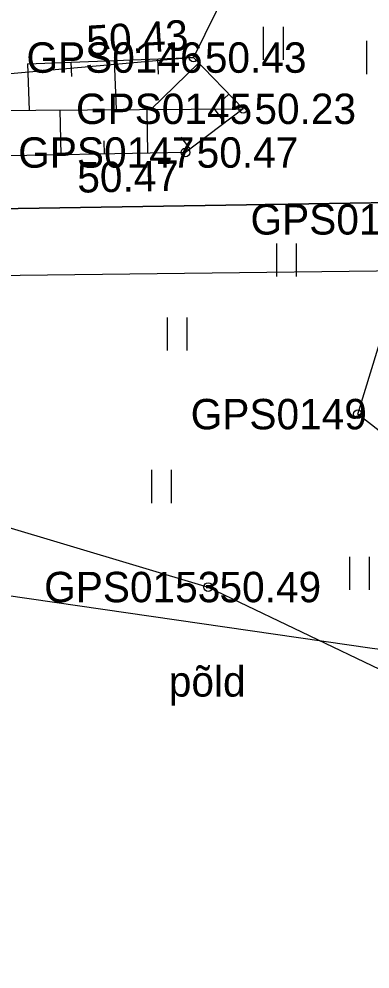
# Model space of a CAD drawing. Extents: x 551623 to 559850, y 6561220 to 6567135.
# Drawn here: x 555977.24 to 555985.32, y 6565343.22 to 6565365.09 of the extents above; entities that cross this region are included whole.
import ezdxf

# ---------------------------------------------------------------- set-up
doc = ezdxf.new("R2010")
doc.units = 0
for name, color, linetype in [('HALJASTUS', 7, 'Continuous'), ('KORGUS-EH2000', 7, 'Continuous'), ('KPOHULIIN', 7, 'Continuous'), ('MOOTKORG-EH2000', 7, 'Continuous'), ('MOOTMPUNKT', 7, 'Continuous'), ('MOOTNR', 7, 'Continuous'), ('MOOTPIIR', 7, 'Continuous'), ('PIIR', 7, 'Continuous'), ('RELJEEF', 7, 'Continuous')]:
    doc.layers.add(name, color=color, linetype=linetype)

msp = doc.modelspace()

# ---------------------------------------------------------------- linework, layer by layer
at = {"layer": 'HALJASTUS'}
for p, q in [((555982.865, 6565364.914), (555982.865, 6565364.153)), ((555983.32, 6565364.914), (555983.32, 6565364.153)), ((555985.243, 6565364.585), (555985.243, 6565363.823)), ((555983.168, 6565359.924), (555983.168, 6565359.162)), ((555983.623, 6565359.924), (555983.623, 6565359.162)), ((555980.649, 6565358.222), (555980.649, 6565357.461)), ((555981.104, 6565358.222), (555981.104, 6565357.461)), ((555980.288, 6565354.709), (555980.288, 6565353.947)), ((555980.743, 6565354.709), (555980.743, 6565353.947)), ((555984.853, 6565352.708), (555984.853, 6565351.947)), ((555985.308, 6565352.708), (555985.308, 6565351.947))]:
    msp.add_line(p, q, dxfattribs=at)
msp.add_lwpolyline([(555785.422, 6565354.502), (555797.657, 6565356.597), (555822.006, 6565356.167), (555839.027, 6565357.099), (555858.223, 6565356.795), (555871.496, 6565354.829), (555880.675, 6565355.554), (555884.247, 6565356.161), (555900.004, 6565357.858), (555919.022, 6565357.654), (555943.248, 6565358.425), (555955.251, 6565358.554), (555967.126, 6565356.336), (555981.596, 6565352.013), (555991.477, 6565347.286)], dxfattribs=at)
at = {"layer": 'KORGUS-EH2000'}
for centre in [(555981.259, 6565364.203), (555981.07, 6565362.017), (555985.042, 6565355.994), (555981.596, 6565352.013)]:
    msp.add_circle(centre, 0.1, dxfattribs=at)
at = {"layer": 'KPOHULIIN'}
msp.add_lwpolyline([(555766.29, 6565358.132), (555774.476, 6565357.809), (555774.476, 6565357.809), (555822.758, 6565358.143), (555870.36, 6565358.416), (555918.911, 6565358.624), (555918.911, 6565358.624), (555966.511, 6565359.063), (556012.012, 6565359.614), (556063.102, 6565345.172), (556063.102, 6565345.172), (556112.628, 6565331.115), (556160.567, 6565309.951), (556211.02, 6565287.529)], dxfattribs=at)
at = {"layer": 'MOOTMPUNKT'}
for centre in [(555981.259, 6565364.203), (555982.4, 6565363.023), (555981.07, 6565362.017), (555985.042, 6565355.994), (555981.596, 6565352.013)]:
    msp.add_circle(centre, 0.1, dxfattribs=at)
at = {"layer": 'MOOTPIIR'}
for points in [[(556057.929, 6565353.821), (556039.198, 6565356.19), (556028.747, 6565357.937), (556026.171, 6565358.357), (556019.769, 6565359.212), (556019.902, 6565364.745), (556021.558, 6565374.265), (556015.152, 6565374.331), (556012.73, 6565375.394), (555993.907, 6565375.821), (555986.511, 6565374.867), (555981.259, 6565364.203), (555966.865, 6565362.926), (555942.733, 6565362.646), (555918.997, 6565362.459), (555899.983, 6565361.794), (555880.558, 6565361.528), (555870.644, 6565361.764), (555852.219, 6565361.421)], [(555839.435, 6565355.215), (555871.496, 6565354.829), (555900.084, 6565356.085), (555918.855, 6565355.549), (555942.97, 6565356.268), (555966.756, 6565353.298), (555985.371, 6565350.605), (555996.731, 6565349.216), (556009.016, 6565348.025), (556019.674, 6565346.939), (556026.62, 6565346.439), (556031.505, 6565345.235), (556038.736, 6565344.782), (556063.163, 6565343.594)]]:
    msp.add_lwpolyline(points, dxfattribs=at)
at = {"layer": 'PIIR'}
for points in [[(555860.69, 6565787.05), (556134.83, 6565867.67), (556136.76, 6565868.24), (556138.68, 6565868.81), (556304.72, 6565917.64), (556407.28, 6565947.65), (556409.2, 6565948.21), (556411.12, 6565948.77), (556555.39, 6565990.98), (556602.55, 6565855.41), (556340.11, 6565662.55), (556145.23, 6565518.55), (556122.95, 6565328.71), (556065.95, 6565349.3), (555986.85, 6565360.88), (555889.86, 6565359.34), (555877.35, 6565546.73)], [(555766.77, 6565362.31), (555785.15, 6565359.9), (555792.17, 6565359.86), (555889.86, 6565359.34), (555986.85, 6565360.88), (556065.95, 6565349.3), (556122.95, 6565328.71), (556199.38, 6565295.85), (556198.85, 6565282.81), (556195.83, 6565275.41), (556189.32, 6565262.35), (556176.88, 6565235.57), (556133.25, 6565139.15), (556097.67, 6565060.64), (555982.17, 6564796.57), (555965.54, 6564731.83), (555935.2, 6564801.96), (555871.92, 6565015.39), (555870.22, 6565021.13), (555867.36, 6565030.76)]]:
    msp.add_lwpolyline(points, close=True, dxfattribs=at)
at = {"layer": 'RELJEEF'}
for p, q in [((555977.434, 6565364.06), (555977.474, 6565362.992)), ((555978.433, 6565364.098), (555978.446, 6565363.768)), ((555979.433, 6565364.135), (555979.475, 6565363.005)), ((555981.379, 6565364.079), (555980.273, 6565363.01)), ((555980.432, 6565364.172), (555980.445, 6565363.824)), ((555982.074, 6565363.361), (555981.968, 6565363.258)), ((555978.208, 6565361.963), (555978.189, 6565362.997)), ((555980.207, 6565362.001), (555980.189, 6565363.009)), ((555981.977, 6565362.703), (555981.738, 6565363.019)), ((555979.208, 6565361.982), (555979.202, 6565362.288)), ((555981.179, 6565362.1), (555980.973, 6565362.373))]:
    msp.add_line(p, q, dxfattribs=at)
for points in [[(555977.434, 6565364.06), (555981.259, 6565364.203), (555982.4, 6565363.023), (555981.07, 6565362.017), (555966.438, 6565361.744), (555942.559, 6565361.46), (555918.67, 6565361.158), (555899.588, 6565360.623), (555880.605, 6565360.164), (555870.862, 6565359.746), (555858.243, 6565359.74), (555839.055, 6565359.56), (555820.21, 6565359.553), (555797.755, 6565359.993), (555784.547, 6565360.474), (555784.137, 6565361.851), (555784.785, 6565363.462), (555797.779, 6565363.82), (555819.876, 6565363.911), (555838.744, 6565363.561), (555851.243, 6565363.431)], [(556009.016, 6565348.025), (555996.731, 6565349.216), (555990.772, 6565351.516), (555985.042, 6565355.994), (555986.421, 6565360.478), (555993.466, 6565364.067), (556008.789, 6565362.217), (556014.135, 6565355.019), (556011.283, 6565351.084), (556009.016, 6565348.025)], [(555785.165, 6565362.242), (555796.742, 6565361.819), (555819.94, 6565361.437), (555839.062, 6565361.413), (555858.506, 6565361.425), (555870.644, 6565361.764), (555880.558, 6565361.528), (555899.983, 6565361.794), (555918.997, 6565362.459), (555942.733, 6565362.646), (555966.865, 6565362.926), (555982.4, 6565363.023)]]:
    msp.add_lwpolyline(points, dxfattribs=at)

# ---------------------------------------------------------------- texts
at = {"layer": 'HALJASTUS'}
msp.add_text('põld', height=0.7, dxfattribs=at).set_placement((555980.689, 6565349.491))
at = {"layer": 'KORGUS-EH2000'}
for s, rotation, p in [(' 50.43', 3.5114, (555978.556, 6565364.219)), (' 50.47', 1.0685, (555978.326, 6565361.088))]:
    msp.add_text(s, height=0.7, rotation=rotation, dxfattribs=at).set_placement(p)
msp.add_text(' 50.49', height=0.7, dxfattribs=at).set_placement((555981.596, 6565351.663))
at = {"layer": 'MOOTKORG-EH2000'}
for s, p in [(' 50.43', (555981.259, 6565363.853)), (' 50.23', (555982.4, 6565362.673)), (' 50.47', (555981.07, 6565361.667)), (' 50.49', (555981.596, 6565351.663))]:
    msp.add_text(s, height=0.7, dxfattribs=at).set_placement(p)
at = {"layer": 'MOOTNR'}
for s, p in [('GPS0146 ', (555977.409, 6565363.853)), ('GPS0145 ', (555978.55, 6565362.673)), ('GPS0147 ', (555977.22, 6565361.667)), ('GPS0148 ', (555982.571, 6565360.128)), ('GPS0149 ', (555981.193, 6565355.644)), ('GPS0153 ', (555977.817, 6565351.663))]:
    msp.add_text(s, height=0.7, dxfattribs=at).set_placement(p)

doc.saveas('drawing.dxf')
